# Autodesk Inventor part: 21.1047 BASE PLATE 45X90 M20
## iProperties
Created: 2007-03
Part Number: 21.1047 BASE PLATE 45X90 M20
Document SubType Name: Modeling
Designer: Andy Moles
Material: Aluminum-6061
Mass: 142.147 g
Surface Area: 129.023 cm^2
Volume: 52.4529 cm^3
Density: 2.71 g/cm^3
Author: Andy Moles
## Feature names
1. Extrusion1
2. Hole1
3. Hole2
4. Fillet1
